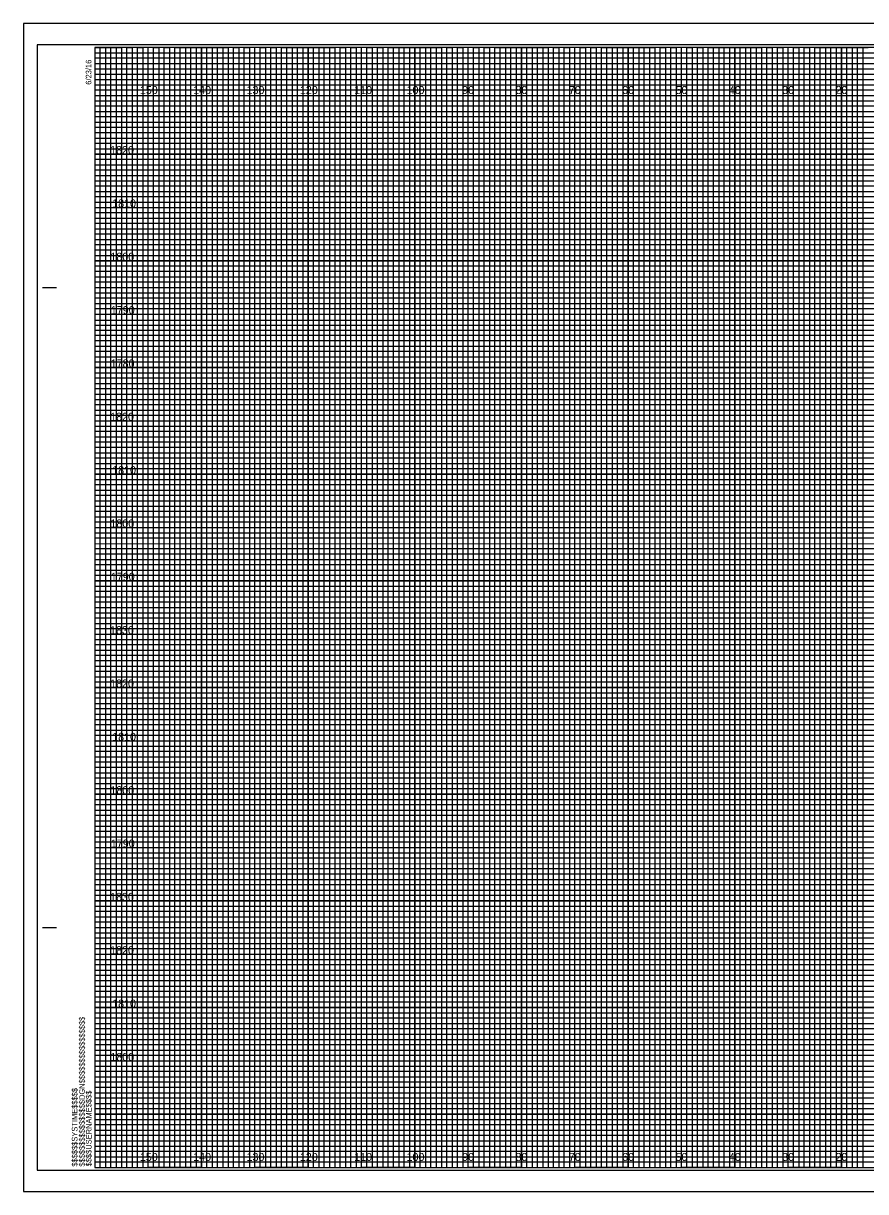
# Model space of a CAD drawing. Extents: x -13 to 323, y -5 to 874.
# Drawn here: x -13.4 to 144.5, y 215.5 to 434.5 of the extents above; entities that cross this region are included whole.
import ezdxf

# ---------------------------------------------------------------- set-up
doc = ezdxf.new("R2010")
doc.units = 0
for name, color, linetype in [('Prop XS Earthwork Shape', 7, 'Continuous'), ('Raster_Level_0', 7, 'Continuous'), ('Scratch_Level_1', 7, 'Continuous'), ('Scratch_Level_3', 7, 'Continuous'), ('Sheet Cross Section CELL', 7, 'Continuous'), ('Sheet Cross Section Grid Minor 1 CELL', 7, 'Continuous'), ('Sheet Cross Section Grid Minor 2 CELL', 7, 'Continuous'), ('Sheet Cutting Line CELL', 7, 'Continuous'), ('Sheet DOT Grid CELL', 7, 'Continuous'), ('Sheet Plot Border Inside CELL', 7, 'Continuous'), ('Sheet Plot Border Outside CELL', 7, 'Continuous')]:
    doc.layers.add(name, color=color, linetype=linetype)

msp = doc.modelspace()

# ---------------------------------------------------------------- linework, layer by layer
at = {"layer": 'Prop XS Earthwork Shape'}
for points in [[(0, 430), (5, 430), (5, 220), (15, 220), (15, 430), (25, 430), (25, 220), (35, 220), (35, 430), (45, 430), (45, 220), (55, 220), (55, 430), (65, 430), (65, 220), (75, 220), (75, 430), (85, 430), (85, 220), (95, 220), (95, 430), (105, 430), (105, 220), (115, 220), (115, 430), (125, 430), (125, 220), (135, 220), (135, 430), (145, 430)], [(0, 425), (275, 425)], [(0, 405), (320, 405), (320, 415), (0, 415)], [(0, 385), (320, 385), (320, 395), (0, 395)], [(0, 365), (320, 365), (320, 375), (0, 375)], [(0, 345), (320, 345), (320, 355), (0, 355)], [(0, 325), (320, 325), (320, 335), (0, 335)], [(0, 305), (320, 305), (320, 315), (0, 315)], [(0, 285), (320, 285), (320, 295), (0, 295)], [(0, 265), (320, 265), (320, 275), (0, 275)], [(0, 245), (320, 245), (320, 255), (0, 255)], [(0, 225), (320, 225), (320, 235), (0, 235)]]:
    msp.add_lwpolyline(points, dxfattribs=at)
at = {"layer": 'Scratch_Level_1'}
for p, q in [((10, 430), (0, 430)), ((10, 220), (10, 430)), ((30, 430), (20, 430)), ((20, 430), (20, 220)), ((30, 220), (30, 430)), ((50, 430), (40, 430)), ((40, 430), (40, 220)), ((50, 220), (50, 430)), ((70, 430), (60, 430)), ((60, 430), (60, 220)), ((70, 220), (70, 430)), ((90, 430), (80, 430)), ((80, 430), (80, 220)), ((90, 220), (90, 430)), ((110, 430), (100, 430)), ((100, 430), (100, 220)), ((110, 220), (110, 430)), ((130, 430), (120, 430)), ((120, 430), (120, 220)), ((130, 220), (130, 430)), ((150, 430), (140, 430)), ((140, 430), (140, 220)), ((20, 220), (10, 220)), ((40, 220), (30, 220)), ((60, 220), (50, 220)), ((80, 220), (70, 220)), ((100, 220), (90, 220)), ((120, 220), (110, 220)), ((140, 220), (130, 220))]:
    msp.add_line(p, q, dxfattribs=at)
for points in [[(0, 420), (320, 420), (320, 410), (0, 410)], [(0, 400), (320, 400), (320, 390), (0, 390)], [(0, 380), (320, 380), (320, 370), (0, 370)], [(0, 360), (320, 360), (320, 350), (0, 350)], [(0, 340), (320, 340), (320, 330), (0, 330)], [(0, 320), (320, 320), (320, 310), (0, 310)], [(0, 300), (320, 300), (320, 290), (0, 290)], [(0, 280), (320, 280), (320, 270), (0, 270)], [(0, 260), (320, 260), (320, 250), (0, 250)], [(0, 240), (320, 240), (320, 230), (0, 230)]]:
    msp.add_lwpolyline(points, dxfattribs=at)
at = {"layer": 'Sheet Cross Section CELL'}
for p, q in [((-9.8, 385), (-7.3, 385)), ((-9.7, 385), (-7.2, 385)), ((-9.8, 265), (-7.3, 265)), ((-9.7, 265), (-7.2, 265)), ((0, 220), (0, 220)), ((0, 220), (0, 220)), ((0, 220), (0, 220)), ((0, 220), (0, 220)), ((0, 220), (0, 220)), ((0, 220), (0, 220)), ((0, 220), (0, 220))]:
    msp.add_line(p, q, dxfattribs=at)
msp.add_lwpolyline([(320, 430), (0, 430), (0, 220), (320, 220)], close=True, dxfattribs=at)
at = {"layer": 'Sheet Cross Section Grid Minor 1 CELL'}
for p, q in [((0, 429), (260, 429)), ((260, 427.98), (0, 427.98)), ((0, 427.98), (0, 427)), ((0, 427), (260, 427)), ((260, 425.89), (0, 425.89)), ((0, 425.89), (0, 424)), ((0, 424), (320, 424))]:
    msp.add_line(p, q, dxfattribs=at)
for points in [[(0, 423), (270, 423), (320, 423), (320, 422), (0, 422)], [(0, 421), (320, 421), (320, 419), (0, 419)], [(0, 418), (320, 418), (320, 417), (0, 416.98)], [(0, 416), (320, 416), (320, 414), (0, 414)], [(0, 413), (320, 413), (320, 412), (0, 412)], [(0, 411), (320, 411), (320, 409), (0, 409)], [(0, 408), (320, 408), (320, 407), (0, 407)], [(0, 406), (320, 406), (320, 404), (0, 404)], [(0, 403), (320, 403), (320, 402), (0, 402)], [(0, 401), (320, 401), (320, 399), (0, 399)], [(0, 398), (320, 398), (320, 397), (0, 397)], [(0, 396), (320, 396), (320, 393.95), (320, 393), (320, 392), (0, 392)], [(0, 394), (320, 394), (320, 393), (0, 393)], [(0, 391), (320, 391), (320, 389), (0, 389.03)], [(0, 389.03), (320, 389), (320, 388), (0, 388)], [(0, 387), (320, 387), (320, 386), (0, 386)], [(0, 384), (320, 384), (320, 383), (0, 383)], [(0, 382), (320, 382), (320, 381), (0, 381)], [(-0.07, 378.89), (320, 378.89), (320, 377.88), (-0.07, 377.88)], [(0, 377), (320, 377), (320, 376), (0, 376)], [(0, 374), (320, 374), (320, 373), (0, 373)], [(0, 372), (320, 372), (320, 371), (0, 371)], [(0, 369), (320, 369), (320, 368), (0, 368)], [(0, 367), (320, 367), (320, 366), (0, 366)], [(0, 364), (320, 364), (320, 363), (0, 363)], [(0, 362), (320, 362), (320, 361), (0, 361)], [(0, 359), (320, 359), (319.99, 357.98), (0, 358)], [(0, 357), (320, 357), (320, 356), (0, 356)], [(0, 354), (320, 354), (320, 353), (0, 353)], [(0, 352), (320, 352), (320, 351), (0, 351)], [(0, 349), (320, 349), (320, 348), (0, 348)], [(0, 347), (320, 347), (320, 346), (0, 346)], [(0, 344), (320, 344), (320, 343), (0, 343)], [(0, 342), (320, 342), (320, 341), (0, 341)], [(0, 339), (320, 339), (320, 338), (0, 338)], [(0, 336.99), (320.07, 336.91), (320, 336), (0, 336)], [(0, 334), (320, 334), (320, 333), (0, 333)], [(0, 332), (320, 332), (320, 331), (0, 331)], [(0, 329), (320, 329), (320, 328), (0, 328)], [(0, 327), (320, 327), (320, 326), (0, 326)], [(0, 324), (320, 324), (320, 323), (0, 323)], [(0, 322), (320, 322), (320, 321), (0, 321)], [(0, 319), (320, 319), (320, 318), (0, 318)], [(0, 317), (320, 317), (320, 316), (0, 316)], [(0, 314), (320, 314), (320, 313), (0, 313)], [(0, 312), (320, 312), (320, 311), (0, 311)], [(0, 309), (320, 309), (320, 308), (0, 308)], [(0, 307), (320, 307), (320, 306), (0, 306)], [(0, 304), (320, 304), (320, 303), (0, 303)], [(0, 302), (320, 302), (320, 301), (0, 301)], [(0, 299), (320, 299), (319.99, 297.98), (0, 298)], [(0, 297), (320, 297), (320, 296), (0, 296)], [(0, 294), (320, 294), (320, 293), (0, 293)], [(0, 292), (320, 292), (320, 291), (0, 291)], [(0, 289), (320, 289), (320, 288), (0, 288)], [(0, 287), (320, 287), (320, 286), (0, 286)], [(0, 284), (320, 284), (320, 283), (0, 283)], [(0, 282), (320, 282), (320, 281), (0, 281)], [(0, 279), (320, 279), (320, 278), (0, 278)], [(0, 276.99), (320.07, 276.91), (320, 276), (0, 276)], [(0, 274), (320, 274), (320, 273), (0, 273)], [(0, 272), (320, 272), (320, 271), (0, 271)], [(0, 269), (320, 269), (320, 268), (0, 268)], [(0, 267), (320, 267), (320, 266), (0, 266)], [(0, 264), (320, 264), (320, 263), (0, 263)], [(0, 262), (320, 262), (320, 261), (0, 261)], [(0, 259), (320, 259), (320, 258), (0, 258)], [(0, 257), (320, 257), (320, 256), (0, 256)], [(0, 254), (320, 254), (320, 253), (0, 253)], [(0, 252), (320, 252), (320, 251), (0, 251)], [(0, 249), (320, 249), (320, 248), (0, 248)], [(0, 247), (320, 247), (320, 246), (0, 246)], [(0, 244), (320, 244), (320, 243), (0, 243)], [(0, 242), (320, 242), (320, 241), (0, 241)], [(0, 239), (320, 239), (320, 238), (0, 238)], [(0, 237), (320, 237), (320, 236), (0, 236)], [(0, 234), (320, 234), (320, 233), (0, 233)], [(0, 232), (320, 232), (320, 231), (0, 231)], [(0, 229), (320, 229), (320, 228), (0, 228)], [(0, 227), (320, 227), (320, 226), (0, 226)], [(0, 224), (320, 224), (320, 223), (0, 223)], [(0, 222), (320, 222), (320, 221), (0, 221)]]:
    msp.add_lwpolyline(points, dxfattribs=at)
at = {"layer": 'Sheet Cross Section Grid Minor 2 CELL'}
for points in [[(0, 220), (1, 220), (1, 430), (2, 430), (2, 220)], [(2, 220), (3, 220), (3, 430), (4, 430), (4, 220)], [(5, 220), (6, 220), (6, 430), (7, 430), (7, 220)], [(7, 220), (8, 220), (8, 430), (9, 430), (9, 220)], [(10, 220), (11, 220), (11, 430), (12, 430), (12, 220)], [(12, 220), (13, 220), (13, 430), (14, 430), (14, 220)], [(15, 220), (16, 220), (16, 430), (17, 430), (17, 220)], [(17, 220), (18, 220), (18, 430), (19, 430), (19, 220)], [(20, 220), (21, 220), (21, 430), (22, 430), (22, 220)], [(22, 220), (23, 220), (23, 430), (24, 430), (24, 220)], [(25, 220), (26, 220), (26, 430), (27, 430), (27, 220)], [(27, 220), (28, 220), (28, 430), (29, 430), (29, 220)], [(30, 220), (31, 220), (31, 430), (32, 430), (32, 220)], [(32, 220), (33, 220), (33, 430), (34, 430), (34, 220)], [(35, 220), (36, 220), (36, 430), (37, 430), (37, 220)], [(37, 220), (38, 220), (38, 430), (39, 430), (39, 220)], [(40, 220), (41, 220), (41, 430), (42, 430), (42, 220)], [(42, 220), (43, 220), (43, 430), (44, 430), (44, 220)], [(45, 220), (46, 220), (46, 430), (47, 430), (47, 220)], [(47, 220), (48, 220), (48, 430), (49, 430), (49, 220)], [(50, 220), (51, 220), (51, 430), (52, 430), (52, 220)], [(52, 220), (53, 220), (53, 430), (54, 430), (54, 220)], [(55, 220), (56, 220), (56, 430), (57, 430), (57, 220)], [(57, 220), (58, 220), (58, 430), (59, 430), (59, 220)], [(60, 220), (61, 220), (61, 430), (62, 430), (62, 220)], [(62, 220), (63, 220), (63, 430), (64, 430), (64, 220)], [(65, 220), (66, 220), (66, 430), (67, 430), (67, 220)], [(67, 220), (68, 220), (68, 430), (69, 430), (69, 220)], [(70, 220), (71, 220), (71, 430), (72, 430), (72, 220)], [(72, 220), (73, 220), (73, 430), (74, 430), (74, 220)], [(75, 220), (76, 220), (76, 430), (77, 430), (77, 220)], [(77, 220), (78, 220), (78, 430), (79, 430), (79, 220)], [(80, 220), (81, 220), (81, 430), (82, 430), (82, 220)], [(82, 220), (83, 220), (83, 430), (84, 430), (84, 220)], [(85, 220), (86, 220), (86, 430), (87, 430), (87, 220)], [(87, 220), (88, 220), (88, 430), (89, 430), (89, 220)], [(90, 220), (91, 220), (91, 430), (92, 430), (92, 220)], [(92, 220), (93, 220), (93, 430), (94, 430), (94, 220)], [(95, 220), (96, 220), (96, 430), (97, 430), (97, 220)], [(97, 220), (98, 220), (98, 430), (99, 430), (99, 220)], [(100, 220), (101, 220), (101, 430), (102, 430), (102, 220)], [(102, 220), (103, 220), (103, 430), (104, 430), (104, 220)], [(105, 220), (106, 220), (106, 430), (107, 430), (107, 220)], [(107, 220), (108, 220), (108, 430), (109, 430), (109, 220)], [(110, 220), (111, 220), (111, 430), (112, 430), (112, 220)], [(112, 220), (113, 220), (113, 430), (114, 430), (114, 220)], [(115, 220), (116, 220), (116, 430), (117, 430), (117, 220)], [(117, 220), (118, 220), (118, 430), (119, 430), (119, 220)], [(120, 220), (121, 220), (121, 430), (122, 430), (122, 220)], [(122, 220), (123, 220), (123, 430), (124, 430), (124, 220)], [(125, 220), (126, 220), (126, 430), (127, 430), (127, 220)], [(127, 220), (128, 220), (128, 430), (129, 430), (129, 220)], [(130, 220), (131, 220), (131, 430), (132, 430), (132, 220)], [(132, 220), (133, 220), (133, 430), (134, 430), (134, 220)], [(135, 220), (136, 220), (136, 430), (137, 430), (137, 220)], [(137, 220), (138, 220), (138, 430), (139, 430), (139, 220)], [(140, 220), (141, 220), (141, 430), (142, 430), (142, 220)], [(142, 220), (143, 220), (143, 430), (144, 430), (144, 220)]]:
    msp.add_lwpolyline(points, dxfattribs=at)
at = {"layer": 'Sheet Cutting Line CELL'}
for p, q in [((323.3, 434.5), (-13.4, 434.5)), ((-13.4, 434.5), (-13.4, 215.5)), ((-13.4, 215.5), (323.3, 215.5))]:
    msp.add_line(p, q, dxfattribs=at)
at = {"layer": 'Sheet DOT Grid CELL'}
for p, q in [((10, 220), (10, 430)), ((20, 220), (20, 430)), ((30, 220), (30, 430)), ((40, 220), (40, 430)), ((50, 220), (50, 430)), ((60, 220), (60, 430)), ((70, 220), (70, 430)), ((80, 220), (80, 430)), ((90, 220), (90, 430)), ((100, 220), (100, 430)), ((110, 220), (110, 430)), ((120, 220), (120, 430)), ((130, 220), (130, 430)), ((140, 220), (140, 430)), ((0, 420), (320, 420)), ((0, 410), (320, 410)), ((0, 400), (320, 400)), ((0, 390), (320, 390)), ((0, 380), (320, 380)), ((0, 370), (320, 370)), ((0, 360), (320, 360)), ((0, 350), (320, 350)), ((0, 340), (320, 340)), ((0, 330), (320, 330)), ((0, 320), (320, 320)), ((0, 310), (320, 310)), ((0, 300), (320, 300)), ((0, 290), (320, 290)), ((0, 280), (320, 280)), ((0, 270), (320, 270)), ((0, 260), (320, 260)), ((0, 250), (320, 250)), ((0, 240), (320, 240)), ((0, 230), (320, 230))]:
    msp.add_line(p, q, dxfattribs=at)
at = {"layer": 'Sheet Plot Border Inside CELL'}
msp.add_lwpolyline([(-10.8, 219.5), (322.4, 219.5), (322.4, 430.5), (-10.8, 430.5)], close=True, dxfattribs=at)
at = {"layer": 'Sheet Plot Border Outside CELL'}
msp.add_lwpolyline([(-13.4, 215.5), (323.3, 215.5), (323.3, 434.5), (-13.4, 434.5)], close=True, dxfattribs=at)

# ---------------------------------------------------------------- texts
at = {"layer": 'Raster_Level_0'}
for s, p in [('150', (8.44, 421.25)), ('140', (18.44, 421.25)), ('130', (28.44, 421.25)), ('120', (38.44, 421.25)), ('110', (48.62, 421.25)), ('100', (58.44, 421.25)), ('90', (68.86, 421.25)), ('80', (78.86, 421.25)), ('70', (88.86, 421.25)), ('60', (98.86, 421.25)), ('50', (108.86, 421.25)), ('40', (118.86, 421.25)), ('30', (128.86, 421.25)), ('20', (138.86, 421.25)), ('150', (8.44, 221.25)), ('140', (18.44, 221.25)), ('130', (28.44, 221.25)), ('120', (38.44, 221.25)), ('110', (48.62, 221.25)), ('100', (58.44, 221.25)), ('90', (68.86, 221.25)), ('80', (78.86, 221.25)), ('70', (88.86, 221.25)), ('60', (98.86, 221.25)), ('50', (108.86, 221.25)), ('40', (118.86, 221.25)), ('30', (128.86, 221.25)), ('20', (138.86, 221.25))]:
    msp.add_text(s, height=1.5, dxfattribs=at).set_placement(p)
at = {"layer": 'Scratch_Level_3'}
for s, p in [('1820', (2.87, 410)), ('1810', (3.25, 400)), ('1800', (2.92, 390)), ('1790', (3, 380)), ('1780', (2.98, 370)), ('1820', (2.87, 360)), ('1810', (3.25, 350)), ('1800', (2.92, 340)), ('1790', (3, 330)), ('1830', (2.86, 320)), ('1820', (2.87, 310)), ('1810', (3.25, 300)), ('1800', (2.92, 290)), ('1790', (3, 280)), ('1830', (2.86, 270)), ('1820', (2.87, 260)), ('1810', (3.25, 250)), ('1800', (2.92, 240))]:
    msp.add_text(s, height=1.5, dxfattribs=at).set_placement(p)
at = {"layer": 'Sheet Cross Section CELL'}
for s, p in [('6/23/16', (-0.65, 423)), ('$$$$$$$$$$$$$$$$DGN$$$$$$$$$$$$$$$$', (-1.88, 220.18)), ('$$$$$$SYSTIME$$$$$', (-3.26, 220.18)), ('$$$$USERNAME$$$$', (-0.62, 220.23))]:
    msp.add_text(s, height=1.05, rotation=90, dxfattribs=at).set_placement(p)

doc.saveas('drawing.dxf')
